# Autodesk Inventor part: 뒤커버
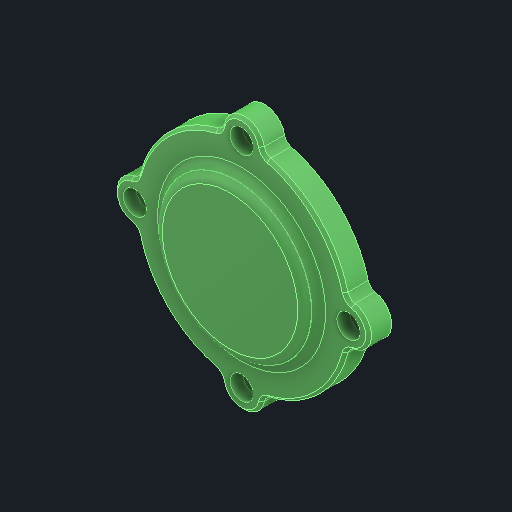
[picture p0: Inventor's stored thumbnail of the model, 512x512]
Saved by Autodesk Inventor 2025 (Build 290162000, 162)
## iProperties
Created: 2025-08
Part Number: 뒤커버
Material: 알루미늄 6061
Document SubType Name: Modeling
Designer: infra17
Density: 2.71 g/cm^3
Appearance: 기본값
Company: 한국ATC센터
Author: jhkim
Sending System: Autodesk Inventor 2026
Preprocessor: ST-DEVELOPER v20.1
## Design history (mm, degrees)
feature "솔리드1"
node "솔리드2"
